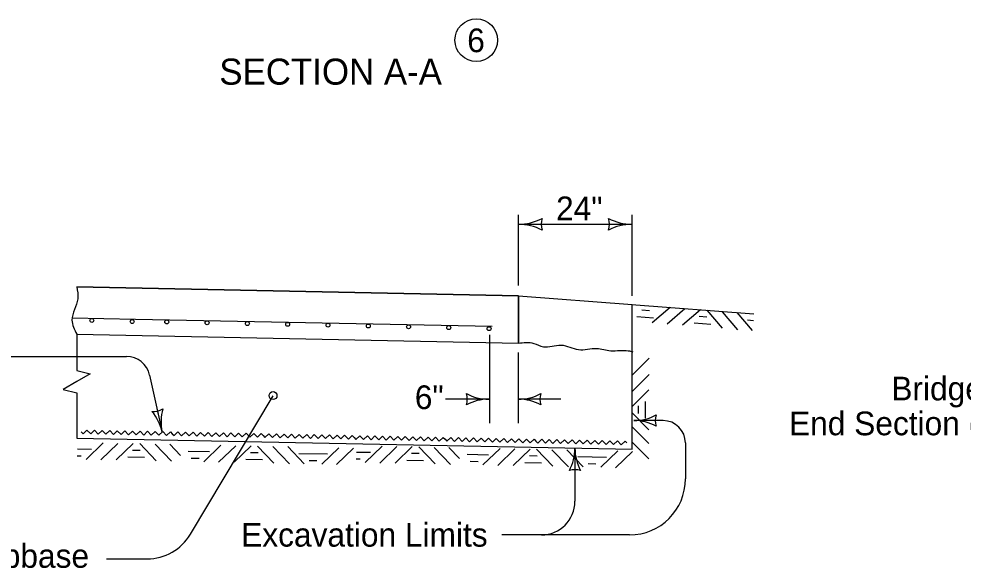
# Model space of a CAD drawing. Extents: x -2135039 to -2120895, y -2139150 to -2136566.
# Drawn here: x -2123840 to -2123042, y -2137940 to -2137477 of the extents above; entities that cross this region are included whole.
import ezdxf

# ---------------------------------------------------------------- set-up
doc = ezdxf.new("R2010")
doc.units = 0
doc.layers.add('Level 2', color=7, linetype='Continuous')
doc.layers.add('Level 3', color=7, linetype='Continuous')

msp = doc.modelspace()

# ---------------------------------------------------------------- linework, layer by layer
at = {"layer": 'Level 2'}
for p, q in [((-2123417.92, -2137701.9), (-2123417.92, -2137642.2)), ((-2123321.92, -2137710.47), (-2123321.92, -2137642.2)), ((-2123417.92, -2137650.18), (-2123321.92, -2137650.18)), ((-2123417.92, -2137710.47), (-2123790.85, -2137702.98)), ((-2123790.85, -2137702.98), (-2123417.92, -2137710.47)), ((-2123417.92, -2137750.47), (-2123417.92, -2137710.47)), ((-2123417.92, -2137710.47), (-2123417.92, -2137750.47)), ((-2123417.92, -2137710.47), (-2123321.92, -2137717.85)), ((-2123322.56, -2137717.86), (-2123219.1, -2137725.82)), ((-2123321.92, -2137840.12), (-2123321.92, -2137717.91)), ((-2123289.65, -2137720.39), (-2123304.84, -2137733.4)), ((-2123277.26, -2137721.57), (-2123292.44, -2137734.58)), ((-2123264.27, -2137722.34), (-2123279.46, -2137735.36)), ((-2123258.88, -2137722.76), (-2123245.86, -2137737.94)), ((-2123245.92, -2137723.98), (-2123232.91, -2137739.17)), ((-2123233.49, -2137724.71), (-2123220.48, -2137739.9)), ((-2123741.38, -2137730.42), (-2123794.82, -2137729.34)), ((-2123440.02, -2137736.46), (-2123741.38, -2137730.42)), ((-2123790.85, -2137742.99), (-2123417.92, -2137750.47)), ((-2123790.85, -2137742.99), (-2123417.92, -2137750.47)), ((-2123790.85, -2137743.25), (-2123790.85, -2137773.51)), ((-2123441.92, -2137818.01), (-2123441.92, -2137743.54)), ((-2123417.92, -2137818.01), (-2123417.92, -2137758.31)), ((-2123857.66, -2137761.72), (-2123748.87, -2137761.72)), ((-2123321.7, -2137777.23), (-2123307.56, -2137763.09)), ((-2123790.85, -2137773.51), (-2123779.51, -2137776.34)), ((-2123779.51, -2137776.34), (-2123790.85, -2137782.96)), ((-2123729.34, -2137777.41), (-2123718.73, -2137825.54)), ((-2123321.7, -2137791.03), (-2123307.56, -2137776.89)), ((-2123790.85, -2137782.96), (-2123802.2, -2137789.58)), ((-2123802.2, -2137789.58), (-2123790.85, -2137792.41)), ((-2123321.92, -2137804.04), (-2123307.78, -2137789.9)), ((-2123790.85, -2137792.41), (-2123790.85, -2137830.73)), ((-2123694.87, -2137911.86), (-2123625.06, -2137795.08)), ((-2123442.91, -2137797.83), (-2123479.45, -2137797.83)), ((-2123382.14, -2137797.83), (-2123417.92, -2137797.83)), ((-2123723.12, -2137805.62), (-2123721.99, -2137810.73)), ((-2123321.92, -2137809.45), (-2123307.78, -2137823.59)), ((-2123321.92, -2137821.03), (-2123307.78, -2137835.17)), ((-2123295.79, -2137815.86), (-2123320.51, -2137815.86)), ((-2123790.85, -2137830.73), (-2123321.94, -2137840.14)), ((-2123768.58, -2137834.75), (-2123783, -2137848.6)), ((-2123756.14, -2137835.22), (-2123770.56, -2137849.08)), ((-2123743.13, -2137835.26), (-2123757.55, -2137849.11)), ((-2123737.72, -2137835.36), (-2123723.86, -2137849.79)), ((-2123724.72, -2137835.85), (-2123710.86, -2137850.27)), ((-2123712.26, -2137835.88), (-2123703.16, -2137845.35)), ((-2123669.05, -2137836.74), (-2123683.47, -2137850.6)), ((-2123656.61, -2137837.22), (-2123671.03, -2137851.07)), ((-2123643.6, -2137837.25), (-2123658.02, -2137851.11)), ((-2123638.19, -2137837.36), (-2123624.33, -2137851.79)), ((-2123625.18, -2137837.85), (-2123611.33, -2137852.27)), ((-2123612.73, -2137837.87), (-2123598.88, -2137852.3)), ((-2123532.98, -2137837.38), (-2123547.4, -2137851.24)), ((-2123520.54, -2137837.86), (-2123534.96, -2137851.71)), ((-2123507.53, -2137837.89), (-2123521.95, -2137851.75)), ((-2123502.12, -2137838), (-2123488.26, -2137852.42)), ((-2123489.12, -2137838.49), (-2123475.26, -2137852.91)), ((-2123476.66, -2137838.51), (-2123467.56, -2137847.99)), ((-2123321.92, -2137834.09), (-2123307.78, -2137848.23)), ((-2123276.88, -2137834.77), (-2123276.88, -2137865.12)), ((-2123569.52, -2137838.74), (-2123583.94, -2137852.6)), ((-2123557.07, -2137839.22), (-2123571.5, -2137853.07)), ((-2123433.45, -2137839.38), (-2123447.87, -2137853.24)), ((-2123421, -2137839.86), (-2123435.43, -2137853.71)), ((-2123408, -2137839.89), (-2123422.42, -2137853.75)), ((-2123402.58, -2137840), (-2123388.73, -2137854.42)), ((-2123389.58, -2137840.49), (-2123375.73, -2137854.91)), ((-2123377.13, -2137840.51), (-2123363.28, -2137854.93)), ((-2123370.19, -2137839.17), (-2123370.19, -2137884.03)), ((-2123333.92, -2137841.38), (-2123348.34, -2137855.23)), ((-2123321.47, -2137841.85), (-2123335.9, -2137855.71)), ((-2123324.15, -2137912.39), (-2123431.92, -2137912.39)), ((-2123765.67, -2137932.57), (-2123731.39, -2137932.57))]:
    msp.add_line(p, q, dxfattribs=at)
for points in [[(-2123313.64, -2137722.4), (-2123307.13, -2137722.9)], [(-2123317.91, -2137727.95), (-2123303.76, -2137729.03)], [(-2123269.52, -2137733.33), (-2123255.37, -2137734.41)], [(-2123265.25, -2137727.78), (-2123258.74, -2137728.28)], [(-2123224.36, -2137730.9), (-2123219.52, -2137731.28)], [(-2123316.43, -2137810.01), (-2123316.43, -2137803.48)], [(-2123310.57, -2137813.84), (-2123310.57, -2137799.65)], [(-2123787.04, -2137825.4), (-2123785.47, -2137827.03), (-2123782.21, -2137823.9), (-2123779.07, -2137827.16), (-2123775.81, -2137824.02), (-2123772.68, -2137827.29), (-2123769.41, -2137824.15), (-2123766.28, -2137827.42), (-2123763.01, -2137824.28), (-2123759.88, -2137827.55), (-2123756.61, -2137824.41), (-2123753.48, -2137827.67), (-2123750.22, -2137824.54), (-2123747.08, -2137827.8), (-2123743.82, -2137824.67), (-2123740.68, -2137827.93), (-2123737.42, -2137824.8), (-2123734.28, -2137828.06), (-2123731.02, -2137824.92), (-2123727.88, -2137828.19), (-2123724.62, -2137825.05), (-2123721.49, -2137828.32), (-2123718.22, -2137825.18), (-2123715.09, -2137828.44), (-2123711.82, -2137825.31), (-2123710.26, -2137826.94)], [(-2123710.26, -2137826.94), (-2123708.69, -2137828.57), (-2123705.42, -2137825.44), (-2123702.29, -2137828.7), (-2123699.03, -2137825.57), (-2123695.89, -2137828.83), (-2123692.63, -2137825.69), (-2123689.49, -2137828.96), (-2123686.23, -2137825.82), (-2123683.09, -2137829.09), (-2123679.83, -2137825.95), (-2123676.69, -2137829.21), (-2123673.43, -2137826.08), (-2123670.3, -2137829.34), (-2123667.03, -2137826.21), (-2123663.9, -2137829.47), (-2123660.63, -2137826.34), (-2123657.5, -2137829.6), (-2123654.24, -2137826.47), (-2123651.1, -2137829.73), (-2123647.84, -2137826.59), (-2123644.7, -2137829.86), (-2123641.44, -2137826.72), (-2123638.3, -2137829.99), (-2123635.04, -2137826.85), (-2123633.47, -2137828.48)], [(-2123633.47, -2137828.48), (-2123631.9, -2137830.11), (-2123628.64, -2137826.98), (-2123625.51, -2137830.24), (-2123622.24, -2137827.11), (-2123619.11, -2137830.37), (-2123615.84, -2137827.24), (-2123612.71, -2137830.5), (-2123609.44, -2137827.36), (-2123606.31, -2137830.63), (-2123603.05, -2137827.49), (-2123599.91, -2137830.76), (-2123596.65, -2137827.62), (-2123593.51, -2137830.88), (-2123590.25, -2137827.75), (-2123587.11, -2137831.01), (-2123583.85, -2137827.88), (-2123580.71, -2137831.14), (-2123577.45, -2137828.01), (-2123574.32, -2137831.27), (-2123571.05, -2137828.13), (-2123567.92, -2137831.4), (-2123564.65, -2137828.26), (-2123561.52, -2137831.53), (-2123558.25, -2137828.39), (-2123556.69, -2137830.02)], [(-2123556.65, -2137830.12), (-2123555.08, -2137831.76), (-2123551.82, -2137828.62), (-2123548.69, -2137831.88), (-2123545.42, -2137828.75), (-2123542.29, -2137832.01), (-2123539.02, -2137828.88), (-2123535.89, -2137832.14), (-2123532.63, -2137829.01), (-2123529.49, -2137832.27), (-2123526.23, -2137829.13), (-2123523.09, -2137832.4), (-2123519.83, -2137829.26), (-2123516.69, -2137832.53), (-2123513.43, -2137829.39), (-2123510.29, -2137832.66), (-2123507.03, -2137829.52), (-2123503.9, -2137832.78), (-2123500.63, -2137829.65), (-2123497.5, -2137832.91), (-2123494.23, -2137829.78), (-2123491.1, -2137833.04), (-2123487.83, -2137829.91), (-2123484.7, -2137833.17), (-2123481.44, -2137830.03), (-2123479.87, -2137831.67)], [(-2123479.87, -2137831.67), (-2123478.3, -2137833.3), (-2123475.04, -2137830.16), (-2123471.9, -2137833.43), (-2123468.64, -2137830.29), (-2123465.5, -2137833.55), (-2123462.24, -2137830.42), (-2123459.1, -2137833.68), (-2123455.84, -2137830.55), (-2123452.71, -2137833.81), (-2123449.44, -2137830.68), (-2123446.31, -2137833.94), (-2123443.04, -2137830.8), (-2123439.91, -2137834.07), (-2123436.64, -2137830.93), (-2123433.51, -2137834.2), (-2123430.25, -2137831.06), (-2123427.11, -2137834.33), (-2123423.85, -2137831.19), (-2123420.71, -2137834.45), (-2123417.45, -2137831.32), (-2123414.31, -2137834.58), (-2123411.05, -2137831.45), (-2123407.91, -2137834.71), (-2123404.65, -2137831.58), (-2123403.08, -2137833.21)], [(-2123403.08, -2137833.21), (-2123401.52, -2137834.84), (-2123398.25, -2137831.7), (-2123395.12, -2137834.97), (-2123391.85, -2137831.83), (-2123388.72, -2137835.1), (-2123385.45, -2137831.96), (-2123382.32, -2137835.22), (-2123379.06, -2137832.09), (-2123375.92, -2137835.35), (-2123372.66, -2137832.22), (-2123369.52, -2137835.48), (-2123366.26, -2137832.35), (-2123363.12, -2137835.61), (-2123359.86, -2137832.47), (-2123356.72, -2137835.74), (-2123353.46, -2137832.6), (-2123350.33, -2137835.87), (-2123347.06, -2137832.73), (-2123343.93, -2137835.99), (-2123340.66, -2137832.86), (-2123337.53, -2137836.12), (-2123334.27, -2137832.99), (-2123331.13, -2137836.25), (-2123327.87, -2137833.12), (-2123326.3, -2137834.75)], [(-2123790.42, -2137845.58), (-2123787.15, -2137845.65)], [(-2123790.3, -2137839.79), (-2123778.27, -2137840.03)], [(-2123747.75, -2137846.52), (-2123733.56, -2137846.8)], [(-2123743.8, -2137840.74), (-2123737.27, -2137840.87)], [(-2123696.8, -2137841.66), (-2123678.74, -2137842.02)], [(-2123644.27, -2137842.74), (-2123637.73, -2137842.87)], [(-2123603.26, -2137843.54), (-2123579.21, -2137844.02)], [(-2123554.7, -2137842.42), (-2123542.67, -2137842.66)], [(-2123508.2, -2137843.38), (-2123501.67, -2137843.51)], [(-2123461.2, -2137844.3), (-2123443.14, -2137844.66)], [(-2123408.66, -2137845.38), (-2123402.13, -2137845.51)], [(-2123367.66, -2137846.18), (-2123343.61, -2137846.66)], [(-2123694.15, -2137847.52), (-2123687.62, -2137847.65)], [(-2123648.21, -2137848.52), (-2123634.02, -2137848.8)], [(-2123594.62, -2137849.51), (-2123588.09, -2137849.64)], [(-2123554.82, -2137848.22), (-2123551.55, -2137848.29)], [(-2123512.14, -2137849.16), (-2123497.96, -2137849.44)], [(-2123458.55, -2137850.15), (-2123452.02, -2137850.28)], [(-2123412.61, -2137851.15), (-2123398.42, -2137851.44)], [(-2123359.02, -2137852.15), (-2123352.48, -2137852.28)]]:
    msp.add_lwpolyline(points, dxfattribs=at)
for centre, radius in [((-2123453.47, -2137494.79), 18), ((-2123778.09, -2137731.35), 1.65), ((-2123744.05, -2137732.28), 1.65), ((-2123714.83, -2137732.61), 1.65), ((-2123680.8, -2137733.29), 1.65), ((-2123646.77, -2137733.97), 1.65), ((-2123612.73, -2137734.66), 1.65), ((-2123578.7, -2137735.34), 1.65), ((-2123544.67, -2137736.02), 1.65), ((-2123510.64, -2137736.71), 1.65), ((-2123476.73, -2137737.4), 1.65), ((-2123442.69, -2137738.32), 1.65), ((-2123625.08, -2137794.76), 3.31)]:
    msp.add_circle(centre, radius, dxfattribs=at)
for centre, radius, start, end in [((-2123417.92, -2137607.68), 42.5, 270, 298.07249), ((-2123382.29, -2137650.18), 16.42, 162.26665, 197.73335), ((-2123357.56, -2137650.18), 16.42, 342.26665, 17.73335), ((-2123321.92, -2137607.68), 42.5, 241.92751, 270), ((-2123357.56, -2137650.18), 16.42, 342.26665, 17.73335), ((-2123321.92, -2137607.68), 42.5, 241.92751, 270), ((-2123417.92, -2137692.68), 42.5, 61.92751, 90), ((-2123321.92, -2137692.68), 42.5, 90, 118.07249), ((-2123321.92, -2137692.68), 42.5, 90, 118.07249), ((-2123748.87, -2137781.72), 20, 12.43134, 90), ((-2123476.6, -2137797.83), 15.52, 342.26665, 17.73335), ((-2123442.91, -2137757.66), 40.18, 241.92751, 270), ((-2123476.6, -2137797.83), 15.52, 342.26665, 17.73335), ((-2123442.91, -2137757.66), 40.18, 241.92751, 270), ((-2123442.91, -2137838.01), 40.18, 90, 118.07249), ((-2123442.91, -2137838.01), 40.18, 90, 118.07249), ((-2123417.92, -2137757.66), 40.18, 270, 298.07249), ((-2123417.92, -2137838.01), 40.18, 61.92751, 90), ((-2123384.24, -2137797.83), 15.52, 162.26665, 197.73335), ((-2123725.97, -2137792.64), 15.52, 264.68499, 300.15169), ((-2123679.49, -2137816.9), 40.18, 164.34585, 192.41834), ((-2123757.96, -2137834.18), 40.18, 12.41834, 40.49083), ((-2123320.51, -2137775.68), 40.18, 270, 298.07249), ((-2123320.51, -2137775.68), 40.18, 270, 298.07249), ((-2123286.82, -2137815.86), 15.52, 162.26665, 197.73335), ((-2123286.82, -2137815.86), 15.52, 162.26665, 197.73335), ((-2123320.51, -2137856.03), 40.18, 61.92751, 90), ((-2123320.51, -2137856.03), 40.18, 61.92751, 90), ((-2123295.79, -2137834.76), 18.91, 0, 90), ((-2123410.37, -2137839.17), 40.18, 331.92751, 360), ((-2123330.02, -2137839.17), 40.18, 180, 208.07249), ((-2123370.19, -2137872.86), 15.52, 72.26665, 107.73335), ((-2123324.15, -2137865.13), 47.27, 270, 360), ((-2123398.55, -2137884.03), 28.36, 270, 360), ((-2123731.39, -2137890.03), 42.54, 270, 329.12488)]:
    msp.add_arc(centre, radius, start, end, dxfattribs=at)
for points in [[(-2123790.85, -2137702.98), (-2123790.03, -2137713), (-2123794.91, -2137731.04), (-2123790.85, -2137742.99)], [(-2123790.85, -2137702.98), (-2123790.03, -2137713), (-2123794.91, -2137731.04), (-2123790.85, -2137742.99)], [(-2123417.92, -2137750.47), (-2123404.98, -2137750.68), (-2123396.85, -2137753.55), (-2123382.02, -2137752.12), (-2123367.19, -2137755.94), (-2123351.89, -2137754.99), (-2123339.93, -2137756.9), (-2123325.11, -2137756.9), (-2123321.28, -2137757.86)]]:
    msp.add_spline(points, degree=3, dxfattribs=at)

# ---------------------------------------------------------------- texts
for s, p in [('Bridge Rail', (-2123103.03, -2137798.82)), ('End Section (typ.)', (-2123189.4, -2137828.27))]:
    msp.add_text(s, height=20, dxfattribs=at).set_placement(p)
at = {"layer": 'Level 3'}
for s, height, p in [('6', 20, (-2123461.16, -2137504.9)), ('SECTION A-A', 22, (-2123670.46, -2137532.31)), ('24"', 20, (-2123386.14, -2137646.72)), ('6"', 20, (-2123505.39, -2137806.15)), ('Excavation Limits', 20, (-2123652.01, -2137922.28)), ('Modified Subbase', 20, (-2123994.56, -2137940.13))]:
    msp.add_text(s, height=height, dxfattribs=at).set_placement(p)

doc.saveas('drawing.dxf')
